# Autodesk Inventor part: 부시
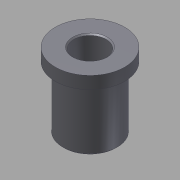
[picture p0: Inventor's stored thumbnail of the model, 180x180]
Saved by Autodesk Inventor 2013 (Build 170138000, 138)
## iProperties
Company: 한국ATC센터
Created: 2015-11
Part Number: 부시
Document SubType Name: Modeling
Designer: mdu
Density: 7.86 g/cm^3
Material: 강철, 연강
Mass: 67.4477 g
Surface Area: 43.1512 cm^2
Volume: 8.58113 cm^3
Author: mdu
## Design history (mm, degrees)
sketch "스케치1"
  geometry: C1 r 11 at (0, 0) reference; C2 r 14 at (0, 0) reference; C3 r 11 at (0, 0) reference; 1 further point
  node "참조1"
  node "참조2"
extrude "돌출1" new body sketch "스케치1" distance "d0" = 5; taper "d1" = 0 deg
extrude "돌출2" join sketch "스케치1" distance "d2" = 25; taper "d3" = 0 deg
hole "구멍1" diameter "d6" = 13; stored, may be unused: countersink angle "d10" = 90 deg, drill point angle "d12" = 118 deg; dims "d4" = 10, "d5" = 10, "d7" = 6, "d8" = 4, "d9" = 2, "d11" = 8
chamfer "모따기1" distance "d13" = 0.5; stored, may be unused: second distance "d14" = 2, angle "d15" = 45 deg
chamfer "모따기2" distance "d16" = 0.5; stored, may be unused: second distance "d17" = 2, angle "d18" = 45 deg
node "솔리드1"
